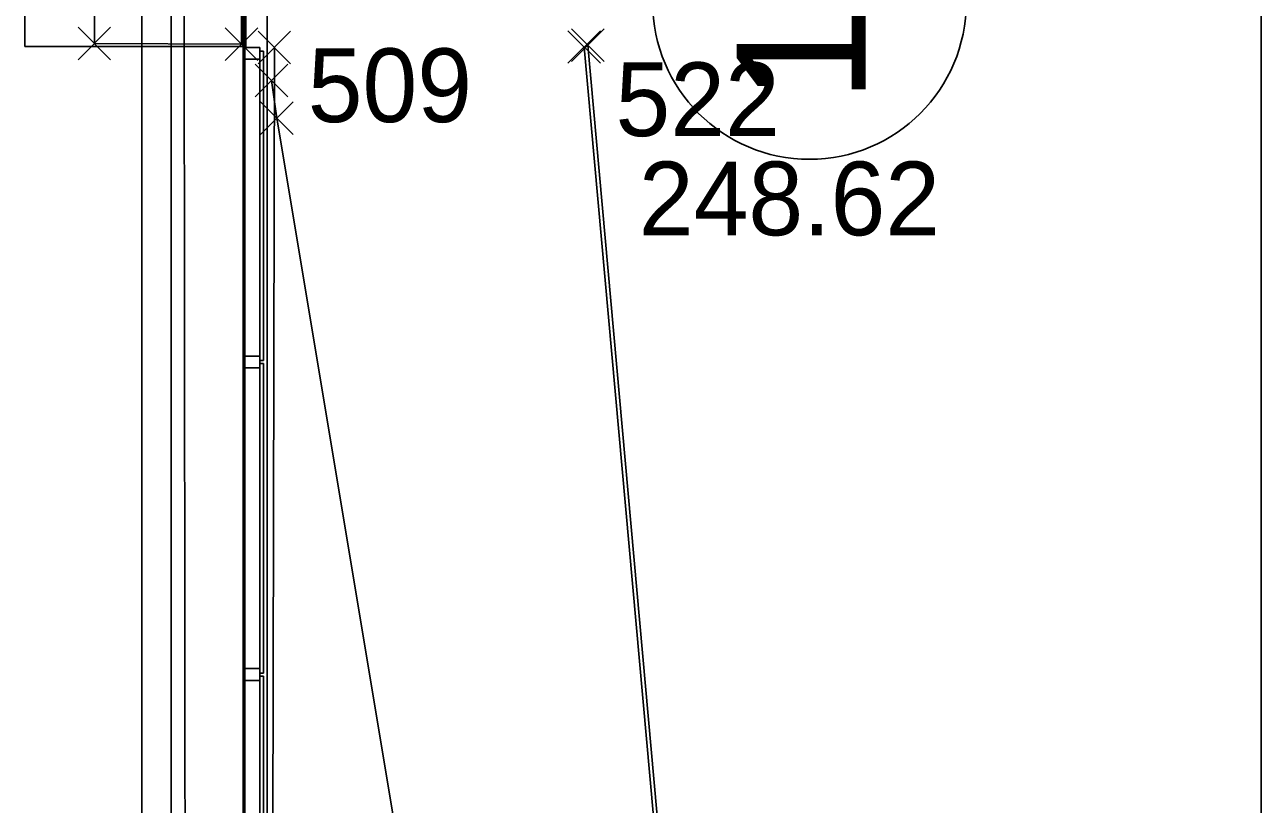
# Model space of a CAD drawing. Extents: x -264205 to -263659, y -1242401 to -1242060.
# Drawn here: x -263796.54 to -263788.14, y -1242173.32 to -1242168.03 of the extents above; entities that cross this region are included whole.
import ezdxf

# ---------------------------------------------------------------- set-up
doc = ezdxf.new("R2010")
doc.units = 0
for name, color, linetype in [('BOD_CISLO', 7, 'Continuous'), ('BOD_SYMBOL', 7, 'Continuous'), ('BOD_VYSKA', 7, 'Continuous'), ('KFA_SO_10-1_BETONOVE_STLPY', 7, 'Continuous'), ('KFA_SO_10-1_PLACHTY', 7, 'Continuous'), ('KFA_SO_10-1_STRECHY', 7, 'Continuous'), ('KFA_SO_10-1_TRIBUNA_C_OBVOD', 7, 'Continuous'), ('OBRUBNIKY_KOMUNIKACIE_PROJEKT', 7, 'Continuous'), ('OSI_STAVBY_KFA', 7, 'Continuous'), ('SITUACIA_DSP_2D', 7, 'Continuous')]:
    doc.layers.add(name, color=color, linetype=linetype)

msp = doc.modelspace()

# ---------------------------------------------------------------- linework, layer by layer
at = {"layer": 'BOD_SYMBOL'}
for p, q in [((-263796.1755, -1242168.2725), (-263795.9545, -1242168.0515)), ((-263795.9545, -1242168.2725), (-263796.1755, -1242168.0515)), ((-263795.1765, -1242168.2765), (-263794.9555, -1242168.0555)), ((-263794.9555, -1242168.2765), (-263795.1765, -1242168.0555)), ((-263792.8255, -1242168.2835), (-263792.6045, -1242168.0625)), ((-263792.6045, -1242168.2835), (-263792.8255, -1242168.0625)), ((-263794.9535, -1242168.2995), (-263794.7325, -1242168.0785)), ((-263794.7325, -1242168.2995), (-263794.9535, -1242168.0785)), ((-263792.8505, -1242168.2955), (-263792.6295, -1242168.0745)), ((-263792.6295, -1242168.2955), (-263792.8505, -1242168.0745)), ((-263794.9725, -1242168.5225), (-263794.7515, -1242168.3015)), ((-263794.7515, -1242168.5225), (-263794.9725, -1242168.3015)), ((-263794.9365, -1242168.7785), (-263794.7155, -1242168.5575)), ((-263794.7155, -1242168.7785), (-263794.9365, -1242168.5575))]:
    msp.add_line(p, q, dxfattribs=at)
at = {"layer": 'KFA_SO_10-1_BETONOVE_STLPY'}
msp.add_lwpolyline([(-263795.065, -1242167.566), (-263795.066, -1242168.166), (-263796.065, -1242168.162), (-263796.063, -1242167.564)], close=True, dxfattribs=at)
at = {"layer": 'KFA_SO_10-1_PLACHTY'}
msp.add_line((-263794.893, -1242195.596), (-263794.843, -1242168.189), dxfattribs=at)
for points in [[(-263795.396, -1242226.823), (-263795.427, -1242195.892), (-263795.456, -1242167.905), (-263795.427, -1242160.909), (-263795.402, -1242132.887), (-263795.428, -1242101.98)], [(-263790.3646, -1242195.4172), (-263794.826, -1242168.6678), (-263794.862, -1242168.412)]]:
    msp.add_lwpolyline(points, dxfattribs=at)
msp.add_lwpolyline([(-263792.74, -1242168.185), (-263792.715, -1242168.173), (-263790.251, -1242195.546), (-263790.271, -1242195.563)], close=True, dxfattribs=at)
at = {"layer": 'KFA_SO_10-1_STRECHY'}
msp.add_line((-263795.734, -1242227.196), (-263795.754, -1242101.588), dxfattribs=at)
at = {"layer": 'KFA_SO_10-1_TRIBUNA_C_OBVOD'}
msp.add_lwpolyline([(-263795.284, -1242101.267), (-263795.051, -1242101.819), (-263795.059, -1242226.991), (-263795.286, -1242227.548)], dxfattribs=at)
at = {"layer": 'OBRUBNIKY_KOMUNIKACIE_PROJEKT'}
msp.add_line((-263794.8928, -1242101.3822), (-263794.8928, -1242227.3822), dxfattribs=at)
at = {"layer": 'OSI_STAVBY_KFA'}
msp.add_line((-263795.5428, -1242083.2372), (-263795.5428, -1242246.7072), dxfattribs=at)
msp.add_circle((-263791.2101, -1242167.8825), 1.0643, dxfattribs=at)
at = {"layer": 'SITUACIA_DSP_2D'}
for p, q in [((-263788.1428, -1242233.636), (-263788.1428, -1242082.6399)), ((-263794.8928, -1242101.3822), (-263794.8928, -1242227.3822)), ((-263795.0428, -1242101.7691), (-263795.0428, -1242226.9954)), ((-263796.5378, -1242167.5823), (-263796.5378, -1242168.1823)), ((-263795.0378, -1242168.1823), (-263795.0378, -1242167.5823)), ((-263796.5378, -1242168.1823), (-263795.0378, -1242168.1823)), ((-263795.0427, -1242168.2673), (-263795.0427, -1242168.1873)), ((-263795.0427, -1242168.1873), (-263794.9427, -1242168.1873)), ((-263794.9427, -1242168.1873), (-263794.9427, -1242168.2273)), ((-263794.9427, -1242170.3123), (-263794.9427, -1242168.2123)), ((-263794.9427, -1242168.2123), (-263794.9177, -1242168.2123)), ((-263794.9427, -1242168.2273), (-263794.9427, -1242168.2673)), ((-263794.9177, -1242168.2123), (-263794.9177, -1242170.3123)), ((-263794.9427, -1242168.2673), (-263795.0427, -1242168.2673)), ((-263794.9427, -1242170.2823), (-263795.0427, -1242170.2823)), ((-263795.0427, -1242170.2823), (-263795.0427, -1242170.3623)), ((-263794.9427, -1242170.2723), (-263794.9427, -1242170.2823)), ((-263794.9427, -1242170.3623), (-263794.9427, -1242170.2723)), ((-263794.9177, -1242170.3123), (-263794.9427, -1242170.3123)), ((-263794.9177, -1242170.3323), (-263794.9427, -1242170.3323)), ((-263794.9427, -1242170.3323), (-263794.9427, -1242172.4323)), ((-263794.9177, -1242172.4323), (-263794.9177, -1242170.3323)), ((-263795.0427, -1242170.3623), (-263794.9427, -1242170.3623)), ((-263794.9427, -1242172.4023), (-263795.0427, -1242172.4023)), ((-263795.0427, -1242172.4023), (-263795.0427, -1242172.4823)), ((-263794.9427, -1242172.4423), (-263794.9427, -1242172.4023)), ((-263794.9427, -1242172.4323), (-263794.9177, -1242172.4323)), ((-263795.0427, -1242172.4823), (-263794.9427, -1242172.4823)), ((-263794.9427, -1242172.4823), (-263794.9427, -1242172.4423)), ((-263794.9427, -1242174.5523), (-263794.9427, -1242172.4523)), ((-263794.9427, -1242172.4523), (-263794.9177, -1242172.4523)), ((-263794.9177, -1242172.4523), (-263794.9177, -1242174.5523))]:
    msp.add_line(p, q, dxfattribs=at)

# ---------------------------------------------------------------- texts
at = {"layer": 'BOD_CISLO'}
for s, p in [('509', (-263794.6165, -1242168.6946)), ('522', (-263792.5271, -1242168.7896))]:
    msp.add_text(s, height=0.5, dxfattribs=at).set_placement(p)
at = {"layer": 'BOD_VYSKA'}
msp.add_text('248.62', height=0.5, dxfattribs=at).set_placement((-263792.3685, -1242169.4624))
at = {"layer": 'OSI_STAVBY_KFA'}
msp.add_text('14', height=0.875, rotation=90, dxfattribs=at).set_placement((-263790.8295, -1242168.5623))

doc.saveas('drawing.dxf')
